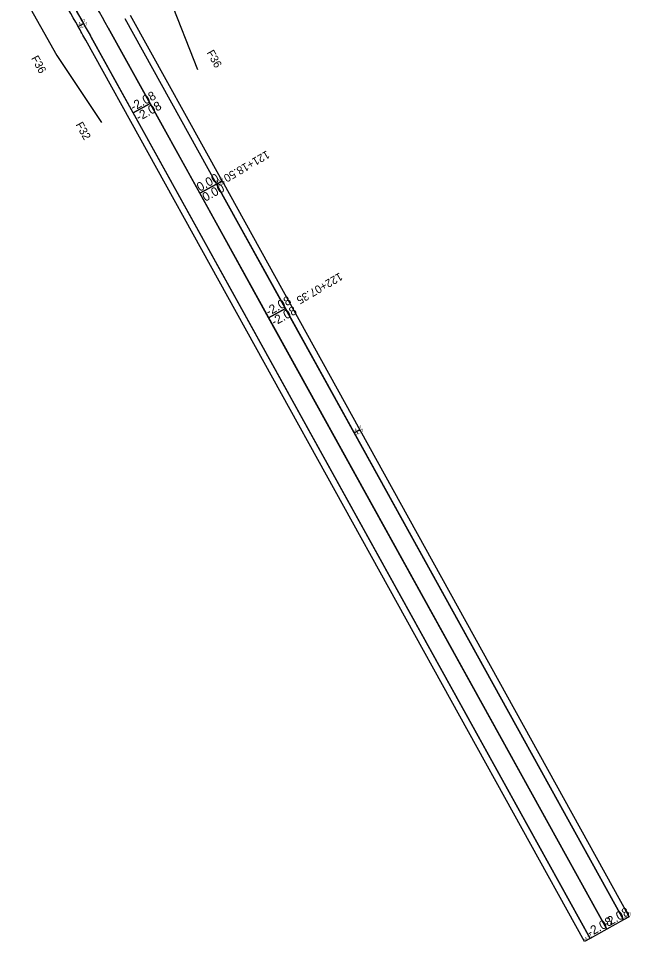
# Model space of a CAD drawing. Extents: x 2163527 to 2171930, y 206045 to 210376.
# Drawn here: x 2171548 to 2171930, y 206045 to 206622 of the extents above; entities that cross this region are included whole.
import ezdxf

# ---------------------------------------------------------------- set-up
doc = ezdxf.new("R2010")
doc.units = 0
for name, color, linetype in [('Default', 7, 'Continuous'), ('RD_PD_CstnLmt', 7, 'Continuous'), ('RD_PD_TX_CstnLmt', 7, 'Continuous'), ('RD_SHT_TX', 7, 'Continuous')]:
    doc.layers.add(name, color=color, linetype=linetype)

msp = doc.modelspace()

# ---------------------------------------------------------------- linework, layer by layer
at = {"layer": 'Default'}
for p, q in [((2171675.03, 206520.11), (2171617.82, 206623.59)), ((2171585.07, 206616.64), (2171588.56, 206618.59)), ((2171585.07, 206616.64), (2171588.56, 206618.59)), ((2171614.32, 206621.65), (2171671.53, 206518.17)), ((2171614.32, 206621.65), (2171671.53, 206518.17)), ((2171661.03, 206512.36), (2171603.82, 206615.84)), ((2171603.82, 206615.84), (2171630.04, 206568.41)), ((2171901.3, 206044.73), (2171589.82, 206608.1)), ((2171619.54, 206562.6), (2171593.32, 206610.04)), ((2171593.32, 206610.04), (2171904.8, 206046.67)), ((2171630.04, 206568.41), (2171619.54, 206562.6)), ((2171619.54, 206562.6), (2171630.04, 206568.41)), ((2171630.04, 206568.41), (2171915.3, 206052.48)), ((2171904.8, 206046.67), (2171619.54, 206562.6)), ((2171671.53, 206518.17), (2171675.03, 206520.11)), ((2171671.53, 206518.17), (2171675.03, 206520.11)), ((2171675.03, 206520.11), (2171761.02, 206364.59)), ((2171671.53, 206518.17), (2171661.03, 206512.36)), ((2171661.03, 206512.36), (2171671.53, 206518.17)), ((2171757.52, 206362.66), (2171671.53, 206518.17)), ((2171671.53, 206518.17), (2171714.52, 206440.41)), ((2171704.02, 206434.61), (2171661.03, 206512.36)), ((2171714.52, 206440.41), (2171704.02, 206434.61)), ((2171704.02, 206434.61), (2171714.52, 206440.41)), ((2171714.52, 206440.41), (2171925.8, 206058.28)), ((2171915.3, 206052.48), (2171704.02, 206434.61)), ((2171761.02, 206364.59), (2171757.52, 206362.66)), ((2171757.52, 206362.66), (2171761.02, 206364.59)), ((2171761.02, 206364.59), (2171929.3, 206060.22)), ((2171925.8, 206058.28), (2171757.52, 206362.66)), ((2171925.8, 206058.28), (2171915.3, 206052.48)), ((2171929.3, 206060.22), (2171925.8, 206058.28)), ((2171915.3, 206052.48), (2171904.8, 206046.67)), ((2171904.8, 206046.67), (2171901.3, 206044.73))]:
    msp.add_line(p, q, dxfattribs=at)
for radius, start, end in [(2200, 28.938, 30.47864), (2200, 28.938, 30.47864), (2184, 29.19435, 30.47864), (2188, 28.938, 30.47864), (2188, 29.19435, 30.47864), (2188, 28.938, 29.19435), (2184, 28.938, 29.19435)]:
    msp.add_arc((2169678.5, 205551.35), radius, start, end, dxfattribs=at)
at = {"layer": 'RD_PD_CstnLmt'}
for p, q in [((2171547.82, 206641.36), (2171571.79, 206598.42)), ((2171641.16, 206636.79), (2171659.57, 206589.83)), ((2171571.79, 206598.42), (2171599.71, 206556.73))]:
    msp.add_line(p, q, dxfattribs=at)

# ---------------------------------------------------------------- texts
at = {"layer": 'Default'}
for s, height, rotation, p in [('-4.17', 1.84, 29.19435, (2171585.07, 206616.97)), ('-4.17', 1.84, 29.19435, (2171586.24, 206614.87)), ('-2.08', 5.52, 28.938, (2171619.56, 206563.57)), ('-2.08', 5.52, 28.938, (2171623.04, 206557.27)), ('0.00', 5.52, 28.938, (2171661.05, 206513.33)), ('0.00', 1.84, 28.938, (2171671.54, 206518.49)), ('0.00', 1.84, 28.938, (2171672.7, 206516.39)), ('0.00', 5.52, 28.938, (2171664.53, 206507.03)), ('-2.08', 5.52, 28.938, (2171704.04, 206435.57)), ('-2.08', 5.52, 28.938, (2171707.52, 206429.27)), ('-4.17', 1.84, 28.938, (2171757.52, 206362.98)), ('-4.17', 1.84, 28.938, (2171758.68, 206360.88)), ('-2.08', 5.52, 28.938, (2171915.32, 206053.44)), ('-2.08', 5.52, 28.938, (2171904.81, 206047.64)), ('-4.17', 1.84, 28.938, (2171925.81, 206058.6)), ('-4.17', 1.84, 28.938, (2171901.3, 206045.06))]:
    msp.add_text(s, height=height, rotation=rotation, dxfattribs=at).set_placement(p)
at = {"layer": 'RD_PD_TX_CstnLmt'}
for s, rotation, p in [('F36', 298.938, (2171665.21, 206600.3)), ('F36', 298.94468, (2171555.55, 206596.8)), ('F32', 298.938, (2171583.35, 206555.31))]:
    msp.add_text(s, height=5, rotation=rotation, dxfattribs=at).set_placement(p)
at = {"layer": 'RD_SHT_TX'}
for s, p in [('121+18.50', (2171702.88, 206539.32)), ('122+07.35', (2171748.45, 206463.07))]:
    msp.add_text(s, height=5, rotation=210.22318, dxfattribs=at).set_placement(p)

doc.saveas('drawing.dxf')
